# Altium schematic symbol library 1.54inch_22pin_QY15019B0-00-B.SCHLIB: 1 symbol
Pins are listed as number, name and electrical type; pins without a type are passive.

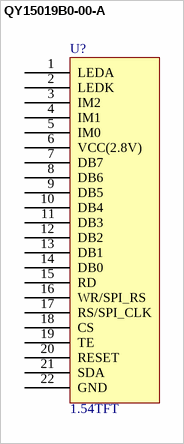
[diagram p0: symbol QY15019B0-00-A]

## QY15019B0-00-A
designator U?, comment 1.54TFT
1.54 TFT IPS
footprint 1.54-QY15019B0-00-A (1.54 TFT IPS)
pins: 1 LEDA, 2 LEDK, 3 IM2, 4 IM1, 5 IM0, 6 VCC(2.8V), 7 DB7, 8 DB6, 9 DB5, 10 DB4, 11 DB3, 12 DB2, 13 DB1, 14 DB0, 15 RD, 16 WR/SPI_RS, 17 RS/SPI_CLK, 18 CS, 19 TE, 20 RESET, 21 SDA, 22 GND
